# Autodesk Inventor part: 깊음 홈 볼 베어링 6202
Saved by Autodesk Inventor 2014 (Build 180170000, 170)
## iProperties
Created: 2025-06
Part Number: 깊음 홈 볼 베어링 6202
Material: 강철, 연강
Document SubType Name: Modeling
Designer: dg
Density: 7.86 g/cm^3
Appearance: 강철
Mass: 45.8724 g
Surface Area: 51.5584 cm^2
Volume: 5.83618 cm^3
Author: jhkim
Description: 깊은 그루브 볼 베어링
Creation Date: 2025-05-27
Sending System: Autodesk Inventor 2026
Preprocessor: ST-DEVELOPER v20.1
Author: dg
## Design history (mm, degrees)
node "깊음 홈 볼 베어링 62021"
body "Solid1"
node "Solid1_1"
node "Solid1_2"
node "Solid1_3"
node "Solid1_4"
node "Solid1_5"
node "Solid1_6"
node "Solid1_7"
node "Solid1_8"
node "Solid1_9"
node "기준1"
node "기준2"
node "기준3"
node "기준4"
node "기준5"
node "기준6"
node "기준7"
node "기준8"
node "기준9"
node "기준10"
